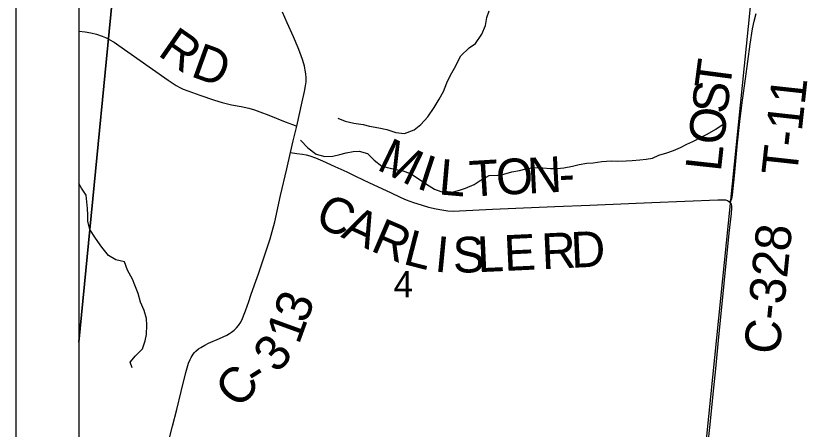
# Model space of a CAD drawing. Extents: x 0 to 34, y 0 to 22.
# Drawn here: x 2 to 3.266, y 17.773 to 18.431 of the extents above; entities that cross this region are included whole.
import ezdxf

# ---------------------------------------------------------------- set-up
doc = ezdxf.new("R2010")
doc.units = 0
for name, color, linetype in [('Default', 7, 'Continuous'), ('GM_X_City_Street', 7, 'Continuous'), ('GM_X_County_Road', 7, 'Continuous'), ('GM_X_County_Road_Text', 7, 'Continuous'), ('GM_X_Minor_River', 7, 'Continuous'), ('GM_X_Section', 7, 'Continuous'), ('GM_X_Section_Text', 7, 'Continuous'), ('GM_X_Township_Road', 7, 'Continuous'), ('GM_X_Township_Road_Text', 7, 'Continuous'), ('SH_Data', 7, 'Continuous')]:
    doc.layers.add(name, color=color, linetype=linetype)

msp = doc.modelspace()

# ---------------------------------------------------------------- linework, layer by layer
at = {"layer": 'Default'}
for points in [[(2.1, 18.6413), (2.1, 17.9112), (2.1707, 18.6348)], [(2.1, 17.9112), (2.1, 17.5957), (3.0746, 17.5112), (3.1795, 18.5396), (2.1707, 18.6348)]]:
    msp.add_lwpolyline(points, close=True, dxfattribs=at)
at = {"layer": 'GM_X_City_Street'}
msp.add_lwpolyline([(2.1, 19.6388), (2.1, 15.6775)], dxfattribs=at)
at = {"layer": 'GM_X_County_Road'}
for points in [[(2.4471, 18.2553), (2.4523, 18.2773), (2.4548, 18.2892), (2.4595, 18.3104), (2.4614, 18.3197), (2.462, 18.3259), (2.462, 18.3322), (2.4616, 18.3385), (2.4607, 18.3447), (2.4595, 18.3508), (2.4569, 18.3598), (2.4539, 18.3687), (2.4494, 18.3803), (2.4421, 18.3975), (2.4318, 18.4201), (2.4244, 18.4371)], [(2.1, 18.4067), (2.1104, 18.4055), (2.1195, 18.404), (2.1285, 18.4018), (2.1373, 18.3988), (2.1429, 18.3964), (2.1484, 18.3936), (2.1564, 18.3889), (2.1641, 18.3838), (2.2123, 18.3497), (2.2424, 18.3284), (2.2554, 18.3199), (2.2609, 18.3168), (2.2666, 18.3142), (2.2753, 18.3109), (2.2929, 18.3048), (2.3164, 18.2969), (2.3284, 18.2933), (2.3435, 18.2896), (2.3587, 18.2865), (2.3708, 18.2838), (2.3797, 18.2814), (2.3885, 18.2784), (2.4029, 18.2729), (2.4288, 18.2623), (2.4404, 18.2579), (2.4471, 18.2553)], [(2.4371, 18.2133), (2.4414, 18.2318), (2.4471, 18.2553)], [(2.2426, 17.7505), (2.2495, 17.7775), (2.2561, 17.8041), (2.2632, 17.8331), (2.2706, 17.863), (2.2727, 17.8707), (2.2751, 17.878), (2.2775, 17.884), (2.2791, 17.8872), (2.2806, 17.8897), (2.2823, 17.8924), (2.2843, 17.8948), (2.2865, 17.8971), (2.2909, 17.9008), (2.2943, 17.9032), (2.3008, 17.9069), (2.3067, 17.9099), (2.324, 17.9171), (2.3298, 17.9197), (2.3357, 17.9225), (2.3401, 17.925), (2.3433, 17.9273), (2.3477, 17.9307), (2.3514, 17.9343), (2.3546, 17.9381), (2.3581, 17.9435), (2.3609, 17.9492), (2.3636, 17.9558), (2.3657, 17.9615), (2.3684, 17.9688), (2.3708, 17.9762), (2.3742, 17.9862), (2.38, 18.0027), (2.3861, 18.0205), (2.3921, 18.038), (2.399, 18.0583), (2.4048, 18.0759), (2.4083, 18.0877), (2.4121, 18.1028), (2.4216, 18.1451), (2.4315, 18.1874), (2.4371, 18.2133)], [(2.4371, 18.2133), (2.4472, 18.2121), (2.4563, 18.2108), (2.4623, 18.2095), (2.4682, 18.2079), (2.4769, 18.2049), (2.4882, 18.2001), (2.5079, 18.1912), (2.527, 18.1824), (2.5409, 18.1759), (2.5633, 18.1654), (2.5965, 18.1495), (2.6131, 18.1418), (2.6217, 18.1382), (2.6333, 18.1338), (2.6451, 18.13), (2.6571, 18.1266), (2.6692, 18.1237), (2.6784, 18.122), (2.6876, 18.1208), (2.697, 18.1203), (2.7063, 18.1205), (2.759, 18.1231), (2.7961, 18.125), (2.858, 18.1277), (2.9138, 18.1298), (2.9757, 18.132), (3.0129, 18.1337), (3.1176, 18.138), (3.1278, 18.1383), (3.13, 18.1381), (3.1317, 18.1377), (3.1334, 18.1369), (3.1348, 18.136), (3.137, 18.1344)], [(3.137, 18.1344), (3.1382, 18.1328), (3.1389, 18.1311), (3.1394, 18.1282), (3.1395, 18.1252), (3.1388, 18.1161), (3.1353, 18.0851), (3.1272, 18.0048), (3.1178, 17.909), (3.1138, 17.8688), (3.1098, 17.8288), (3.1051, 17.7802), (3.1015, 17.7462), (3.0988, 17.7186), (3.096, 17.6937)]]:
    msp.add_lwpolyline(points, dxfattribs=at)
at = {"layer": 'GM_X_Minor_River'}
for points in [[(2.5127, 18.268), (2.5242, 18.2632), (2.5383, 18.26), (2.553, 18.2579), (2.5629, 18.2555), (2.578, 18.2527), (2.5909, 18.2499), (2.6049, 18.2455), (2.619, 18.2438), (2.6342, 18.2497), (2.6446, 18.258), (2.6558, 18.27), (2.6658, 18.2851), (2.674, 18.2986), (2.681, 18.3107), (2.6864, 18.3243), (2.6923, 18.3368), (2.6985, 18.3477), (2.7086, 18.3674), (2.7217, 18.3801), (2.7317, 18.3872), (2.7421, 18.4016), (2.748, 18.4155), (2.7501, 18.4284), (2.7536, 18.439)], [(2.4532, 18.2331), (2.4648, 18.221), (2.4784, 18.2106), (2.492, 18.207), (2.5049, 18.2076), (2.5156, 18.2101), (2.5259, 18.2127), (2.5369, 18.2148), (2.5468, 18.2154), (2.5597, 18.2119), (2.5706, 18.2015), (2.5826, 18.1918), (2.594, 18.189), (2.6049, 18.1866), (2.6148, 18.1846), (2.6284, 18.1799), (2.642, 18.171), (2.654, 18.1629), (2.6665, 18.1551), (2.6767, 18.1512), (2.6873, 18.1495), (2.6968, 18.151), (2.7063, 18.1535), (2.7159, 18.1564), (2.7296, 18.1623), (2.7392, 18.1691), (2.7537, 18.1769), (2.7674, 18.1775), (2.7769, 18.1792), (2.7895, 18.1829), (2.8021, 18.185), (2.812, 18.1876), (2.8257, 18.1897), (2.839, 18.1891), (2.8515, 18.1878), (2.8621, 18.1881), (2.8728, 18.1891), (2.8865, 18.1916), (2.8972, 18.1945), (2.909, 18.1963), (2.9192, 18.1969), (2.9333, 18.199), (2.9481, 18.2), (2.958, 18.1999), (2.9717, 18.2001), (2.9812, 18.2007), (2.9937, 18.2017), (3.0036, 18.2027), (3.0139, 18.2045), (3.0238, 18.2093), (3.0364, 18.213), (3.0471, 18.2166), (3.0582, 18.2215), (3.0685, 18.2266), (3.0781, 18.2311), (3.0914, 18.2378), (3.101, 18.2426), (3.1144, 18.2508), (3.1278, 18.2594)], [(2.1853, 17.8704), (2.1821, 17.8798), (2.1906, 17.8899), (2.2017, 17.9008), (2.2057, 17.9137), (2.2081, 17.9239), (2.2087, 17.9387), (2.208, 17.9494), (2.2044, 17.962), (2.1985, 17.9749), (2.1945, 17.9887), (2.1893, 18.0024), (2.1857, 18.0119), (2.1779, 18.0261), (2.1731, 18.0394), (2.1591, 18.0426), (2.1474, 18.0496), (2.1369, 18.0627), (2.1268, 18.0772), (2.1175, 18.0906), (2.1146, 18.1043), (2.1148, 18.1142), (2.1141, 18.1241), (2.1127, 18.1348), (2.1117, 18.1454), (2.1047, 18.1569), (2.1, 18.1642)]]:
    msp.add_lwpolyline(points, dxfattribs=at)
at = {"layer": 'GM_X_Section'}
msp.add_lwpolyline([(3.1795, 18.5396), (4.1385, 18.4517), (4.0957, 17.4007), (3.0746, 17.5112)], close=True, dxfattribs=at)
at = {"layer": 'GM_X_Township_Road'}
msp.add_lwpolyline([(3.137, 18.1344), (3.1387, 18.1369), (3.1399, 18.1395), (3.1406, 18.1421), (3.1412, 18.146), (3.1441, 18.1765), (3.1491, 18.229), (3.153, 18.2629), (3.1569, 18.2968), (3.1616, 18.3306), (3.1693, 18.3859), (3.1732, 18.4105), (3.1756, 18.4227), (3.1787, 18.4348)], dxfattribs=at)
at = {"layer": 'SH_Data'}
for p, q in [((2, 21), (2, 14)), ((2.1, 20.9), (2.1, 14.1))]:
    msp.add_line(p, q, dxfattribs=at)

# ---------------------------------------------------------------- texts
at = {"layer": 'GM_X_County_Road_Text'}
for s, height, rotation, p in [('R', 0.0568, 325.1679, (2.2242, 18.3693)), ('D', 0.0568, 340.127, (2.2766, 18.3354)), ('M', 0.0568, 334.1575, (2.5728, 18.187)), ('I', 0.0568, 341.9086, (2.6361, 18.157)), ('L', 0.0568, 355.0031, (2.6721, 18.1469)), ('T', 0.0568, 3.4558, (2.7236, 18.143)), ('O', 0.0568, 2.901, (2.7659, 18.1456)), ('N', 0.0568, 2.8971, (2.8158, 18.1481)), ('-', 0.0568, 2.9001, (2.8658, 18.1507)), ('C', 0.0568, 335.0305, (2.4734, 18.0992)), ('A', 0.0568, 335.2699, (2.516, 18.0794)), ('R', 0.0568, 336.7949, (2.5629, 18.0578)), ('C-328', 0.05682, 84.226, (3.2156, 17.8906)), ('L', 0.0568, 345.6058, (2.6148, 18.0364)), ('E', 0.0568, 2.6796, (2.7783, 18.0248)), ('R', 0.0568, 2.6903, (2.8382, 18.0276)), ('D', 0.0568, 2.6909, (2.8849, 18.0298)), ('I', 0.0568, 354.5179, (2.6655, 18.0241)), ('S', 0.0568, 1.6683, (2.6964, 18.0217)), ('L', 0.0568, 2.6329, (2.7358, 18.0228)), ('3', 0.0568, 70.5976, (2.4626, 17.9397)), ('1', 0.0568, 70.0619, (2.4505, 17.9063)), ('3', 0.0568, 48.968, (2.416, 17.8603)), ('C', 0.0568, 50.0765, (2.3561, 17.8034)), ('-', 0.0568, 32.2751, (2.3826, 17.8361))]:
    msp.add_text(s, height=height, rotation=rotation, dxfattribs=at).set_placement(p)
at = {"layer": 'GM_X_Section_Text'}
msp.add_text('4', height=0.0419, rotation=0, dxfattribs=at).set_placement((2.6014, 17.9827))
at = {"layer": 'GM_X_Township_Road_Text'}
for s, height, rotation, p in [('T', 0.0568, 82.4917, (3.1368, 18.3115)), ('S', 0.0568, 83.6341, (3.1326, 18.2737)), ('T-11', 0.05682, 83.7459, (3.2436, 18.1749)), ('O', 0.0568, 83.7294, (3.1271, 18.224)), ('L', 0.0568, 83.7303, (3.1225, 18.1818))]:
    msp.add_text(s, height=height, rotation=rotation, dxfattribs=at).set_placement(p)

doc.saveas('drawing.dxf')
